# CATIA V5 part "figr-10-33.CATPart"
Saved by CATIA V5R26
Part number: Part1
Bounding box of the stored display mesh (mm): x -193.573 to 205.258, y -140.014 to 12.054, z -96.593 to 19.319
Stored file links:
  D:\_Deepak\CATIA\CATIA V5 2015 Parts Files\Part files\Partfiles\c10_catia_v5_6r2015_prt\figr-10-32-1.CATPart
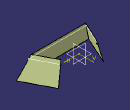
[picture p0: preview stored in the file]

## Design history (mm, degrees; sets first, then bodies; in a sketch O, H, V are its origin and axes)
Body1 (main body)
  Sketch1 on xy-plane, origin (0, 0, 0), H (1, 0, 0), V (0, 1, 0)
    line L1 (-101.4744, 0) -> (-153.3719, -114.1323)
    point P1 (-101.4744, 0)
    line L2 (-153.3719, -114.1323) -> (162.3879, -114.1323)
    line L3 (162.3879, -114.1323) -> (102.3183, 0)
    point P4 (102.3183, 0)
    coincidence: P1 H, P4 H
    horizontal: L2 H
  Sweep1: type Segment, GuideCrv Sketch1, Length1 20, Length2 100, Angle 15, DraftDirection xy-plane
